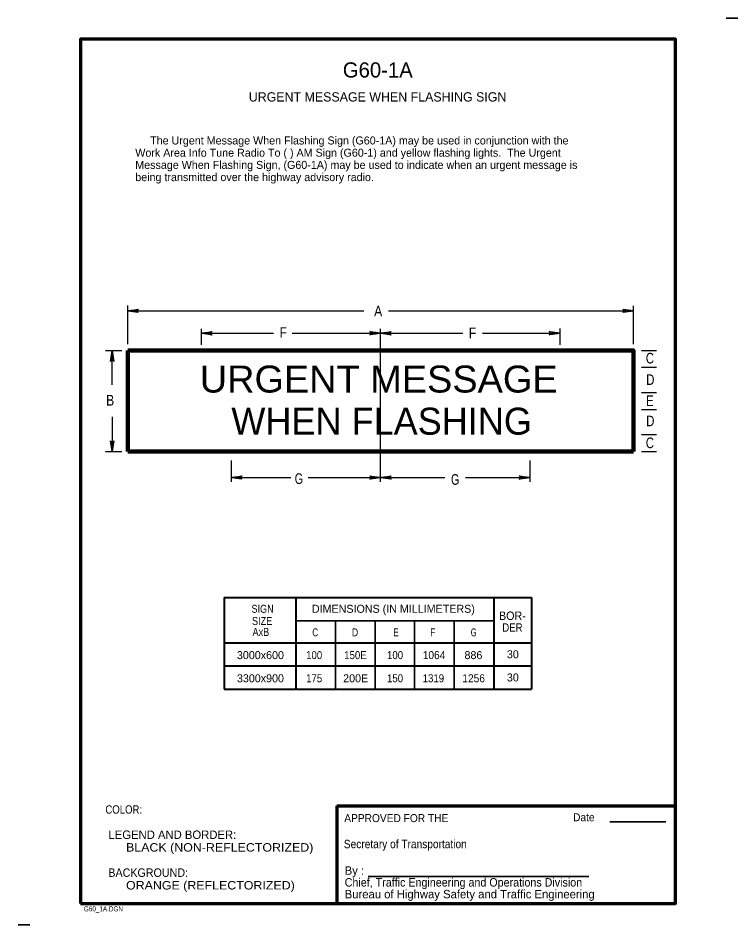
# Model space of a CAD drawing. Extents: x -2.572 to -2.359, y -78.725 to -78.456.
import ezdxf
from ezdxf.enums import TextEntityAlignment as Align

# ---------------------------------------------------------------- set-up
doc = ezdxf.new("R2010")
doc.units = 0
doc.header["$LTSCALE"] = 0.00095
doc.linetypes.add('DOT_DASHED', pattern=[7.7, 5, -1.2, 0.3, -1.2])
doc.layers.add('1', color=7, linetype='Continuous', lineweight=25)
doc.layers.add('3', color=7, linetype='Continuous', lineweight=40)

msp = doc.modelspace()

# ---------------------------------------------------------------- linework, layer by layer
at = {"layer": '1', "lineweight": 35}
for p, q in [((-2.358625, -78.456), (-2.362125, -78.456)), ((-2.396625, -78.6945), (-2.38, -78.6945)), ((-2.46825, -78.71075), (-2.402875, -78.71075)), ((-2.568625, -78.725125), (-2.572125, -78.725125))]:
    msp.add_line(p, q, dxfattribs=at)
at = {"layer": '1'}
for p, q in [((-2.539625, -78.55275), (-2.539625, -78.54125)), ((-2.389625, -78.55275), (-2.389625, -78.541375)), ((-2.539625, -78.542875), (-2.469625, -78.542875)), ((-2.46225, -78.542875), (-2.389625, -78.542875)), ((-2.51775, -78.553), (-2.51775, -78.54825)), ((-2.51775, -78.5495), (-2.496375, -78.5495)), ((-2.464625, -78.553), (-2.464625, -78.54825)), ((-2.434375, -78.5495), (-2.411375, -78.5495)), ((-2.411375, -78.553), (-2.411375, -78.548125)), ((-2.54625, -78.554625), (-2.541375, -78.554625)), ((-2.54425, -78.564875), (-2.54425, -78.554625)), ((-2.38725, -78.554625), (-2.38275, -78.554625)), ((-2.38725, -78.559625), (-2.38275, -78.559625)), ((-2.38725, -78.567125), (-2.38275, -78.567125)), ((-2.38725, -78.572125), (-2.38275, -78.572125)), ((-2.54425, -78.574375), (-2.54425, -78.584625)), ((-2.38725, -78.579625), (-2.38275, -78.579625)), ((-2.54625, -78.584625), (-2.541375, -78.584625)), ((-2.38725, -78.584625), (-2.38275, -78.584625)), ((-2.508875, -78.593625), (-2.508875, -78.58725)), ((-2.464625, -78.593625), (-2.464625, -78.58725)), ((-2.42025, -78.593625), (-2.42025, -78.58725)), ((-2.508875, -78.592375), (-2.49125, -78.592375)), ((-2.439375, -78.592375), (-2.42025, -78.592375))]:
    msp.add_line(p, q, dxfattribs=at)
at = {"layer": '1', "linetype": 'DOT_DASHED'}
msp.add_line((-2.464625, -78.592375), (-2.464625, -78.5495), dxfattribs=at)
at = {"layer": '1', "lineweight": 106}
for q in [(-2.539625, -78.554625), (-2.389625, -78.584625)]:
    msp.add_line((-2.539625, -78.584625), q, dxfattribs=at)
at = {"layer": '1', "lineweight": 70}
for q in [(-2.377125, -78.68975), (-2.477625, -78.71875)]:
    msp.add_line((-2.477625, -78.68975), q, dxfattribs=at)
msp.add_lwpolyline([(-2.553625, -78.71875), (-2.377125, -78.71875), (-2.377125, -78.46225), (-2.553625, -78.46225)], close=True, dxfattribs=at)
at = {"layer": '1'}
for points in [[(-2.536625, -78.54325), (-2.53675, -78.543125), (-2.539625, -78.542875), (-2.536625, -78.54325), (-2.5365, -78.543375), (-2.539625, -78.542875), (-2.53675, -78.54275), (-2.536625, -78.542625), (-2.539625, -78.542875), (-2.5365, -78.542375), (-2.536625, -78.542625)], [(-2.392625, -78.5425), (-2.3925, -78.54275), (-2.389625, -78.542875), (-2.392625, -78.5425), (-2.39275, -78.542375), (-2.389625, -78.542875), (-2.3925, -78.543125), (-2.392625, -78.54325), (-2.389625, -78.542875), (-2.39275, -78.543375), (-2.392625, -78.54325)], [(-2.51475, -78.549875), (-2.514875, -78.54975), (-2.51775, -78.5495), (-2.51475, -78.549875), (-2.514625, -78.550125), (-2.51775, -78.5495), (-2.514875, -78.549375), (-2.51475, -78.54925), (-2.51775, -78.5495), (-2.514625, -78.549), (-2.51475, -78.54925)], [(-2.490875, -78.5495), (-2.464625, -78.5495), (-2.44025, -78.5495)], [(-2.467625, -78.549125), (-2.4675, -78.549375), (-2.464625, -78.5495), (-2.467625, -78.549125), (-2.46775, -78.549), (-2.464625, -78.5495), (-2.4675, -78.54975), (-2.467625, -78.549875), (-2.464625, -78.5495), (-2.46775, -78.55), (-2.467625, -78.549875)], [(-2.461625, -78.549875), (-2.46175, -78.54975), (-2.464625, -78.5495), (-2.461625, -78.549875), (-2.4615, -78.550125), (-2.464625, -78.5495), (-2.46175, -78.549375), (-2.461625, -78.54925), (-2.464625, -78.5495), (-2.4615, -78.549), (-2.461625, -78.54925)], [(-2.414375, -78.549125), (-2.414375, -78.549375), (-2.411375, -78.5495), (-2.414375, -78.549125), (-2.414625, -78.549), (-2.411375, -78.5495), (-2.414375, -78.54975), (-2.414375, -78.549875), (-2.411375, -78.5495), (-2.414625, -78.55), (-2.414375, -78.549875)], [(-2.544625, -78.557625), (-2.544375, -78.5575), (-2.54425, -78.554625), (-2.544625, -78.557625), (-2.54475, -78.557875), (-2.54425, -78.554625), (-2.544125, -78.5575), (-2.543875, -78.557625), (-2.54425, -78.554625), (-2.54375, -78.557875), (-2.543875, -78.557625)], [(-2.543875, -78.581625), (-2.544125, -78.58175), (-2.54425, -78.584625), (-2.543875, -78.581625), (-2.54375, -78.5815), (-2.54425, -78.584625), (-2.544375, -78.58175), (-2.544625, -78.581625), (-2.54425, -78.584625), (-2.54475, -78.5815), (-2.544625, -78.581625)], [(-2.505875, -78.59275), (-2.506, -78.5925), (-2.508875, -78.592375), (-2.505875, -78.59275), (-2.50575, -78.592875), (-2.508875, -78.592375), (-2.506, -78.59225), (-2.505875, -78.592), (-2.508875, -78.592375), (-2.50575, -78.591875), (-2.505875, -78.592)], [(-2.486125, -78.592375), (-2.464625, -78.592375), (-2.4455, -78.592375)], [(-2.467625, -78.592), (-2.4675, -78.59225), (-2.464625, -78.592375), (-2.467625, -78.592), (-2.46775, -78.591875), (-2.464625, -78.592375), (-2.4675, -78.5925), (-2.467625, -78.59275), (-2.464625, -78.592375), (-2.46775, -78.592875), (-2.467625, -78.59275)], [(-2.461625, -78.59275), (-2.46175, -78.5925), (-2.464625, -78.592375), (-2.461625, -78.59275), (-2.4615, -78.592875), (-2.464625, -78.592375), (-2.46175, -78.59225), (-2.461625, -78.592), (-2.464625, -78.592375), (-2.4615, -78.591875), (-2.461625, -78.592)], [(-2.42325, -78.592), (-2.42325, -78.59225), (-2.42025, -78.592375), (-2.42325, -78.592), (-2.4235, -78.591875), (-2.42025, -78.592375), (-2.42325, -78.5925), (-2.42325, -78.59275), (-2.42025, -78.592375), (-2.4235, -78.592875), (-2.42325, -78.59275)]]:
    msp.add_lwpolyline(points, dxfattribs=at)
at = {"layer": '1', "lineweight": 106}
msp.add_lwpolyline([(-2.539625, -78.554625), (-2.389625, -78.554625), (-2.389625, -78.584625)], dxfattribs=at)
at = {"layer": '3'}
for p, q in [((-2.511, -78.628), (-2.419875, -78.628)), ((-2.511, -78.628), (-2.511, -78.655125)), ((-2.48975, -78.628), (-2.48975, -78.655125)), ((-2.431, -78.628), (-2.431, -78.655125)), ((-2.419875, -78.628), (-2.419875, -78.655125)), ((-2.511, -78.641375), (-2.419875, -78.641375)), ((-2.511, -78.64825), (-2.419875, -78.64825)), ((-2.511, -78.655125), (-2.419875, -78.655125))]:
    msp.add_line(p, q, dxfattribs=at)
at = {"layer": '3', "lineweight": 35}
for p, q in [((-2.431, -78.634875), (-2.48975, -78.634875)), ((-2.478, -78.634875), (-2.478, -78.655125)), ((-2.46625, -78.634875), (-2.46625, -78.655125)), ((-2.46625, -78.634875), (-2.46625, -78.64825)), ((-2.4545, -78.634875), (-2.4545, -78.655125)), ((-2.44275, -78.634875), (-2.44275, -78.655125))]:
    msp.add_line(p, q, dxfattribs=at)

# ---------------------------------------------------------------- texts
at = {"layer": '1'}
for s, height, p in [('G60-1A', 0.0045, (-2.465438, -78.473625)), ('URGENT MESSAGE WHEN FLASHING SIGN', 0.00275, (-2.4655, -78.48075))]:
    msp.add_text(s, height=height, dxfattribs=at).set_placement(p, align=Align.CENTER)
for s, height, p in [('     The Urgent Message When Flashing Sign (G60-1A) may be used in conjunction with the', 0.002375, (-2.537375, -78.4935)), ('Work Area Info Tune Radio To ( ) AM Sign (G60-1) and yellow flashing lights.  The Urgent', 0.002375, (-2.537375, -78.497125)), ('Message When Flashing Sign, (G60-1A) may be used to indicate when an urgent message is', 0.002375, (-2.537375, -78.50075)), ('being transmitted over the highway advisory radio.', 0.002375, (-2.537375, -78.504375)), ('WHEN FLASHING', 0.008, (-2.508875, -78.579625)), (' LEGEND AND BORDER:', 0.0025, (-2.54625, -78.699625)), ('By :', 0.0025, (-2.47525, -78.71025)), ('Bureau of Highway Safety and Traffic Engineering', 0.0025, (-2.47525, -78.71725))]:
    msp.add_text(s, height=height, dxfattribs=at).set_placement(p)
for s, width, p in [('A', 0.85, (-2.464125, -78.5445)), ('F', 0.85, (-2.492375, -78.550875)), ('F', 0.85, (-2.43625, -78.551)), ('C', 0.8, (-2.3835, -78.5585)), ('D', 0.8, (-2.383375, -78.564875)), ('B', 0.85, (-2.543625, -78.571)), ('E', 0.8, (-2.383625, -78.571125)), ('D', 0.8, (-2.383375, -78.577125)), ('C', 0.8, (-2.3835, -78.583625)), ('G', 0.75, (-2.487625, -78.59425)), ('G', 0.75, (-2.44125, -78.5945))]:
    msp.add_text(s, height=0.00315, dxfattribs=dict(at, width=width)).set_placement(p, align=Align.RIGHT)
for s, height, width, p in [('URGENT MESSAGE', 0.008004, 1.05, (-2.51825, -78.567125)), ('COLOR:', 0.0025, 0.85, (-2.54625, -78.692125)), ('Date ', 0.002375, 0.95, (-2.4075, -78.694375)), ('APPROVED FOR THE', 0.002375, 0.95, (-2.475375, -78.694625)), ('Secretary of Transportation', 0.0025, 0.9, (-2.4755, -78.702375)), ('      BLACK (NON-REFLECTORIZED)', 0.0025, 1.1, (-2.54625, -78.703375)), (' BACKGROUND:', 0.0025, 0.95, (-2.54625, -78.710875)), ('      ORANGE (REFLECTORIZED)', 0.0025, 1.1, (-2.54625, -78.714625)), ('Chief, Traffic Engineering and Operations Division', 0.0025, 0.95, (-2.47525, -78.71375)), ('G60_1A.DGN', 0.0015, 0.75, (-2.552625, -78.721125))]:
    msp.add_text(s, height=height, dxfattribs=dict(at, width=width)).set_placement(p)
at = {"layer": '3'}
for s, height, width, p in [('SIGN', 0.002375, 0.85, (-2.499625, -78.6325)), ('BOR-', 0.0025, 0.95, (-2.4255, -78.634625)), ('SIZE', 0.002375, 0.85, (-2.49975, -78.636125)), ('DER', 0.0025, 0.85, (-2.4255, -78.638125)), ('AxB', 0.002375, 0.85, (-2.500125, -78.639375)), ('C', 0.002375, 0.75, (-2.484, -78.6395)), ('D', 0.002375, 0.8, (-2.472187, -78.6395)), ('E', 0.002375, 0.75, (-2.460062, -78.6395)), ('F', 0.002375, 0.8, (-2.449125, -78.6395)), ('G', 0.002375, 0.7, (-2.437, -78.6395)), ('100', 0.002375, 0.9, (-2.484313, -78.64625)), ('150E', 0.002375, 0.9, (-2.472062, -78.64625)), ('100', 0.002375, 0.9, (-2.460313, -78.64625)), ('1064', 0.002375, 0.95, (-2.44875, -78.64625)), ('175', 0.002375, 0.9, (-2.484313, -78.653125)), ('150', 0.002375, 0.9, (-2.460313, -78.653125)), ('1319', 0.002375, 0.9, (-2.448937, -78.653125)), ('1256', 0.002375, 0.95, (-2.437, -78.653125))]:
    msp.add_text(s, height=height, dxfattribs=dict(at, width=width)).set_placement(p, align=Align.CENTER)
for s, p in [('DIMENSIONS (IN MILLIMETERS)', (-2.460812, -78.6325)), ('30', (-2.425375, -78.646)), ('3000x600', (-2.50025, -78.64625)), ('886', (-2.437063, -78.64625)), ('3300x900', (-2.50025, -78.653125)), ('200E', (-2.472, -78.653125)), ('30', (-2.425375, -78.652875))]:
    msp.add_text(s, height=0.002375, dxfattribs=at).set_placement(p, align=Align.CENTER)

doc.saveas('drawing.dxf')
